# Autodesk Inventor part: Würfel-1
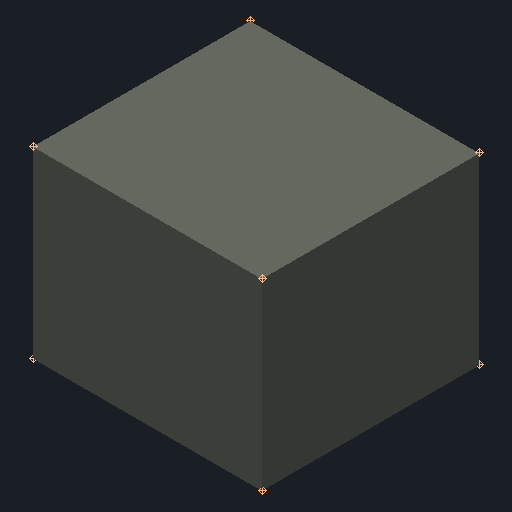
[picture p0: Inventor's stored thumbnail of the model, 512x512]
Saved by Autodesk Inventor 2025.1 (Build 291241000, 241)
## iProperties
Company: Ed. Züblin AG
Created: 2021-07
Part Number: Würfel-1
Material: Stahlbeton C30/37
Document SubType Name: Modeling
Designer: Eimannsmir
Mass: 3.70653 g
Surface Area: 7.83735 cm^2
Volume: 1.48261 cm^3
Density: 2.5 g/cm^3
Appearance: Beton C30/37
z_Bereich: Tunnelbau
z_Direktion: Tief- und Tunnelbau
z_Konzerneinheit: Zentrale Technik
z_Matchkey: 5D-TUB-__-__-__-___-___-___
cpiComponentType: Attribut
cpiFitMatchkey: =<z_Matchkey>
z_Matchkey_010: xxxxx
z_Matchkey_020: 5DTUB
z_Matchkey_030: xxx
z_Matchkey_040: xxx
z_Matchkey_050: xxx
z_Matchkey_060: xxx
z_Matchkey_070: xxx
z_Matchkey_080: xxx
z_Matchkey_090: xxx
z_Matchkey_100: xxx
z_Matchkey_110: xxx
z_Matchkey_120: xxxxxxx
z_Matchkey_130: xxxx
z_Matchkey_140: xxxx
DocNumber: Würfel-1.ipt
Folder: Übung\
VDS_Category: Konstruktion
z_Matchkey_1: 5D
z_Matchkey_2: TUB
z_Matchkey_3: __
z_Matchkey_4: __
z_Matchkey_5: __
z_Matchkey_6: ___
z_Matchkey_7: ___
z_Matchkey_8: ___
d4: 0,010 m
d5: 0,00 grd
Matchkey_1: BIM 5D
Matchkey_2: Tunnelbau
Matchkey_3: Stollen
Matchkey_4: Nord-West
Matchkey_5: Innenschale
Matchkey_7: Anker - IBO-Anker
Matchkey_8: Anker: 4m - 25mm
Matchkey_6: Ulme links
Author: Eimannsmir
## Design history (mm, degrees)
sketch "Skizze3"
  geometry: L1 (-5.887, -5.786)-(6.609, -5.786); L2 (6.609, -5.786)-(6.609, 6.079); L3 (6.609, 6.079)-(-5.887, 6.079); L4 (-5.887, 6.079)-(-5.887, -5.786); 1 further point
  constraints: 8 end point, 2 parallel, 1 horizontal, 1 perpendicular
extrude "Extrusion3" new body sketch "Skizze3" stored distance "d4" = 10; taper "d5" = 0 deg
workpoint "Arbeitspunkt1"
workpoint "Arbeitspunkt2"
workpoint "Arbeitspunkt3"
workpoint "Arbeitspunkt4"
workpoint "Arbeitspunkt5"
workpoint "Arbeitspunkt6"
workpoint "Arbeitspunkt7"
workpoint "Arbeitspunkt8"
node "Volumenkörper3"
node "Volumenkörpern"
node "Oberflächenkörpern"
